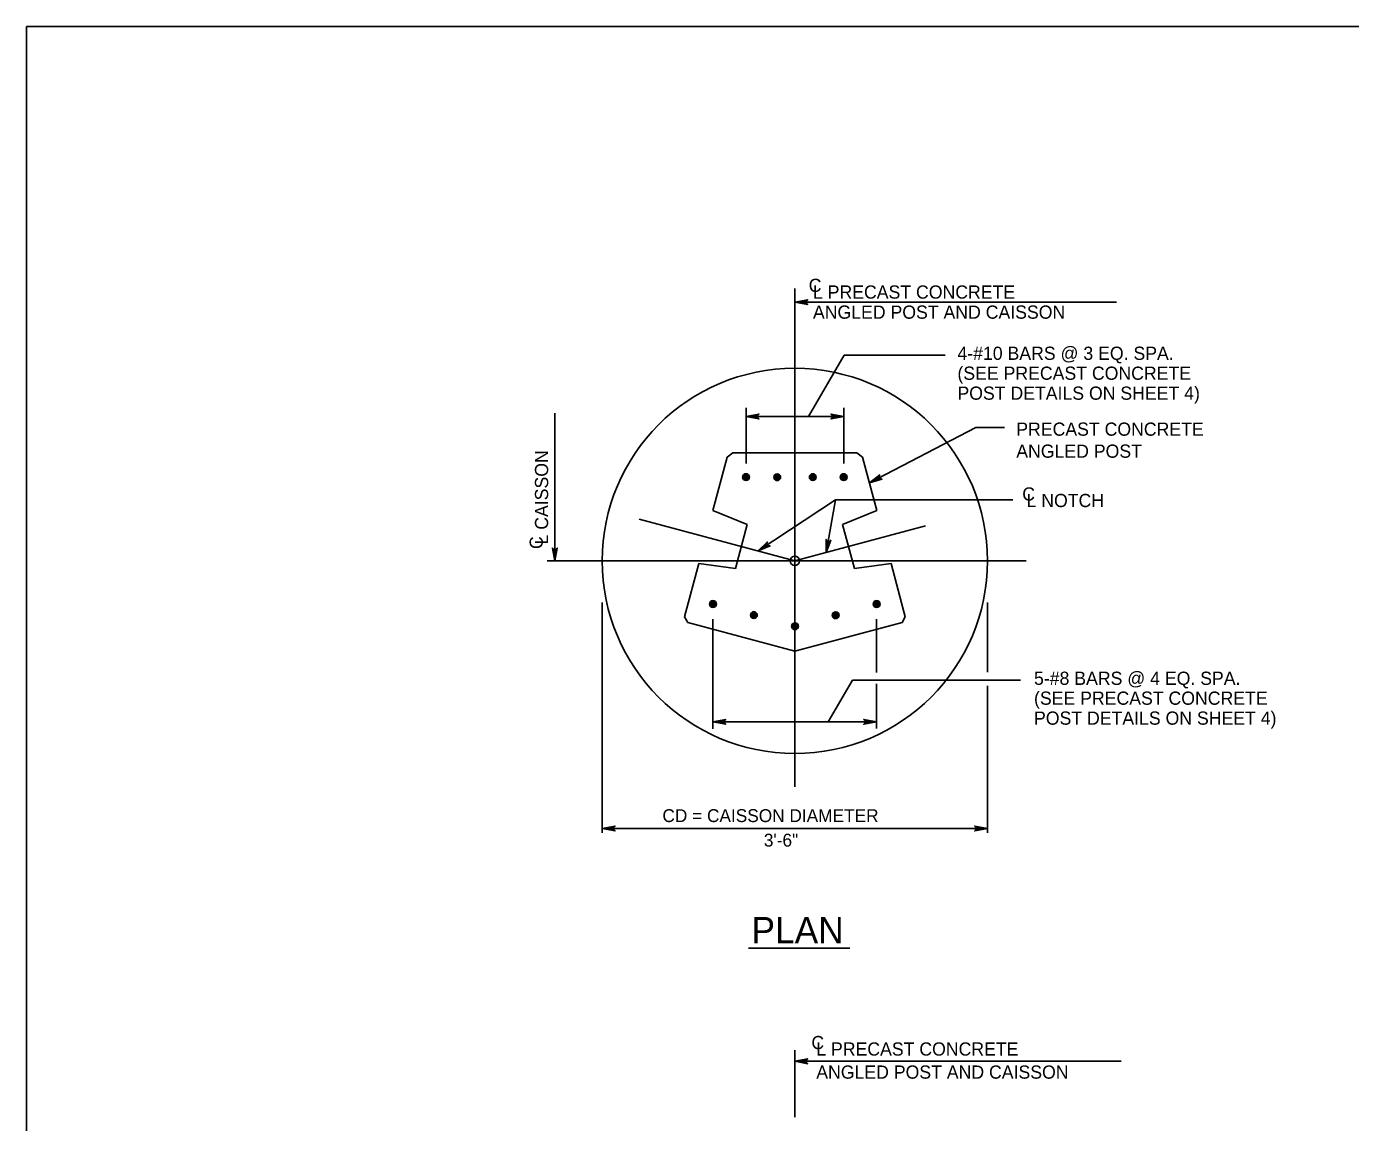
# Model space of a CAD drawing. Extents: x 3351 to 8430, y -3586 to 1457.
# Drawn here: x 3801.3 to 4109.3, y -2668.3 to -2413.3 of the extents above; entities that cross this region are included whole.
import ezdxf

# ---------------------------------------------------------------- set-up
doc = ezdxf.new("R2010")
doc.units = 0
doc.layers.add('1', color=7, linetype='Continuous')
doc.layers.add('2', color=7, linetype='Continuous')

msp = doc.modelspace()

# ---------------------------------------------------------------- linework, layer by layer
at = {"layer": '1'}
for p, q in [((3980.03, -2590.15), (3980.03, -2474.23)), ((3980.03, -2477.43), (4054.86, -2477.43)), ((3983.23, -2504.02), (3991.47, -2489.75)), ((3991.47, -2489.75), (4015, -2489.75)), ((3924.21, -2503.29), (3924.21, -2537.62)), ((3968.67, -2514.98), (3968.67, -2502.03)), ((3991.4, -2514.98), (3991.4, -2502.03)), ((3968.67, -2504.02), (3991.4, -2504.02)), ((3997.37, -2519.48), (4022.14, -2506.61)), ((4022.14, -2506.61), (4028.79, -2506.61)), ((3964.29, -2513.53), (3965.64, -2512.5)), ((3965.64, -2512.5), (3994.43, -2512.5)), ((3994.43, -2512.5), (3995.78, -2513.53)), ((3960.98, -2525.89), (3964.29, -2513.53)), ((3995.78, -2513.53), (3999.09, -2525.89)), ((3989.49, -2523.43), (3971.46, -2535.32)), ((3989.49, -2523.43), (3987.32, -2535.67)), ((3989.49, -2523.43), (4030.76, -2523.43)), ((3943.82, -2527.92), (3980.03, -2537.62)), ((3968.95, -2529.13), (3960.98, -2525.89)), ((3999.09, -2525.89), (3991.12, -2529.13)), ((3966.19, -2539.43), (3968.95, -2529.13)), ((4010.39, -2529.49), (3980.03, -2537.62)), ((3991.12, -2529.13), (3993.88, -2539.43)), ((3922.43, -2537.62), (4033.86, -2537.62)), ((3954.35, -2550.61), (3957.67, -2538.25)), ((3957.67, -2538.25), (3966.19, -2539.43)), ((3980.03, -2537.62), (3980.03, -2537.62)), ((3993.88, -2539.43), (4002.4, -2538.25)), ((4002.4, -2538.25), (4005.71, -2550.61)), ((3935.23, -2547.32), (3935.23, -2600.91)), ((4024.83, -2547.32), (4024.83, -2563.49)), ((3955.11, -2551.92), (3954.35, -2550.61)), ((3980.03, -2558.6), (3955.11, -2551.92)), ((3960.99, -2576.65), (3960.99, -2551.15)), ((4004.96, -2551.92), (3980.03, -2558.6)), ((3999.05, -2563.58), (3999.05, -2551.15)), ((4005.71, -2550.61), (4004.96, -2551.92)), ((3987.81, -2575.05), (3993.41, -2565.36)), ((3993.41, -2565.36), (4032.5, -2565.36)), ((3999.05, -2576.6), (3999.05, -2566.24)), ((4024.83, -2566.65), (4024.83, -2600.91)), ((3960.99, -2575.05), (3999.05, -2575.05)), ((3935.23, -2599.86), (4024.83, -2599.86)), ((3969.28, -2627.74), (3992.81, -2627.74)), ((3980.03, -2651.46), (3980.03, -2667.02)), ((3980.03, -2654.02), (4055.92, -2654.02))]:
    msp.add_line(p, q, dxfattribs=at)
for points in [[(3980.03, -2477.43), (3983.02, -2476.87), (3982.79, -2477.03), (3982.67, -2477.23), (3982.63, -2477.43), (3982.67, -2477.63), (3982.79, -2477.83), (3983.02, -2477.99), (3980.03, -2477.43), (3982.79, -2477.83), (3982.67, -2477.63), (3980.03, -2477.43), (3982.63, -2477.43), (3982.67, -2477.23), (3980.03, -2477.43), (3982.79, -2477.03)], [(3968.67, -2504.02), (3971.66, -2503.46), (3971.43, -2503.62), (3971.31, -2503.82), (3971.27, -2504.02), (3971.31, -2504.22), (3971.43, -2504.42), (3971.66, -2504.58), (3968.67, -2504.02), (3971.43, -2504.42), (3971.31, -2504.22), (3968.67, -2504.02), (3971.27, -2504.02), (3971.31, -2503.82), (3968.67, -2504.02), (3971.43, -2503.62)], [(3991.4, -2504.02), (3988.41, -2504.58), (3988.64, -2504.42), (3988.76, -2504.22), (3988.8, -2504.02), (3988.76, -2503.82), (3988.64, -2503.62), (3988.41, -2503.46), (3991.4, -2504.02), (3988.64, -2503.62), (3988.76, -2503.82), (3991.4, -2504.02), (3988.8, -2504.02), (3988.76, -2504.22), (3991.4, -2504.02), (3988.64, -2504.42)], [(3997.37, -2519.48), (3999.76, -2517.61), (3999.63, -2517.86), (3999.62, -2518.09), (3999.68, -2518.28), (3999.8, -2518.45), (4000, -2518.57), (4000.28, -2518.6), (3997.37, -2519.48), (4000, -2518.57), (3999.8, -2518.45), (3997.37, -2519.48), (3999.68, -2518.28), (3999.62, -2518.09), (3997.37, -2519.48), (3999.63, -2517.86)], [(3971.46, -2535.32), (3973.64, -2533.21), (3973.54, -2533.47), (3973.55, -2533.71), (3973.63, -2533.89), (3973.77, -2534.04), (3973.98, -2534.14), (3974.26, -2534.15), (3971.46, -2535.32), (3973.98, -2534.14), (3973.77, -2534.04), (3971.46, -2535.32), (3973.63, -2533.89), (3973.55, -2533.71), (3971.46, -2535.32), (3973.54, -2533.47)], [(3987.32, -2535.67), (3987.29, -2532.63), (3987.41, -2532.89), (3987.58, -2533.04), (3987.77, -2533.11), (3987.98, -2533.11), (3988.19, -2533.03), (3988.39, -2532.83), (3987.32, -2535.67), (3988.19, -2533.03), (3987.98, -2533.11), (3987.32, -2535.67), (3987.77, -2533.11), (3987.58, -2533.04), (3987.32, -2535.67), (3987.41, -2532.89)], [(3924.21, -2537.62), (3923.65, -2534.64), (3923.81, -2534.87), (3924.01, -2534.99), (3924.21, -2535.02), (3924.41, -2534.99), (3924.61, -2534.87), (3924.77, -2534.64), (3924.21, -2537.62), (3924.61, -2534.87), (3924.41, -2534.99), (3924.21, -2537.62), (3924.21, -2535.02), (3924.01, -2534.99), (3924.21, -2537.62), (3923.81, -2534.87)], [(3960.99, -2575.05), (3963.97, -2574.49), (3963.74, -2574.65), (3963.62, -2574.85), (3963.59, -2575.05), (3963.62, -2575.25), (3963.74, -2575.45), (3963.97, -2575.61), (3960.99, -2575.05), (3963.74, -2575.45), (3963.62, -2575.25), (3960.99, -2575.05), (3963.59, -2575.05), (3963.62, -2574.85), (3960.99, -2575.05), (3963.74, -2574.65)], [(3999.05, -2575.05), (3996.06, -2575.61), (3996.29, -2575.45), (3996.41, -2575.25), (3996.45, -2575.05), (3996.41, -2574.85), (3996.29, -2574.65), (3996.06, -2574.49), (3999.05, -2575.05), (3996.29, -2574.65), (3996.41, -2574.85), (3999.05, -2575.05), (3996.45, -2575.05), (3996.41, -2575.25), (3999.05, -2575.05), (3996.29, -2575.45)], [(3935.23, -2599.86), (3938.22, -2600.42), (3938.1, -2600.34), (3937.99, -2600.26), (3937.93, -2600.16), (3937.87, -2600.06), (3937.85, -2599.96), (3937.83, -2599.86), (3937.85, -2599.76), (3937.87, -2599.66), (3937.93, -2599.56), (3937.99, -2599.46), (3938.1, -2599.38), (3938.22, -2599.3), (3935.23, -2599.86), (3938.1, -2599.38), (3937.99, -2599.46), (3935.23, -2599.86), (3937.93, -2599.56), (3937.87, -2599.66), (3935.23, -2599.86), (3937.85, -2599.76), (3937.83, -2599.86), (3935.23, -2599.86), (3937.85, -2599.96), (3937.87, -2600.06), (3935.23, -2599.86), (3937.93, -2600.16), (3937.99, -2600.26), (3935.23, -2599.86), (3938.1, -2600.34)], [(4024.83, -2599.86), (4021.85, -2599.3), (4021.97, -2599.38), (4022.08, -2599.46), (4022.14, -2599.56), (4022.2, -2599.66), (4022.22, -2599.76), (4022.23, -2599.86), (4022.22, -2599.96), (4022.2, -2600.06), (4022.14, -2600.16), (4022.08, -2600.26), (4021.97, -2600.34), (4021.85, -2600.42), (4024.83, -2599.86), (4021.97, -2600.34), (4022.08, -2600.26), (4024.83, -2599.86), (4022.14, -2600.16), (4022.2, -2600.06), (4024.83, -2599.86), (4022.22, -2599.96), (4022.23, -2599.86), (4024.83, -2599.86), (4022.22, -2599.76), (4022.2, -2599.66), (4024.83, -2599.86), (4022.14, -2599.56), (4022.08, -2599.46), (4024.83, -2599.86), (4021.97, -2599.38)], [(3980.03, -2654.02), (3983.02, -2653.46), (3982.79, -2653.62), (3982.67, -2653.82), (3982.63, -2654.02), (3982.67, -2654.22), (3982.79, -2654.42), (3983.02, -2654.58), (3980.03, -2654.02), (3982.79, -2654.42), (3982.67, -2654.22), (3980.03, -2654.02), (3982.63, -2654.02), (3982.67, -2653.82), (3980.03, -2654.02), (3982.79, -2653.62)]]:
    msp.add_lwpolyline(points, dxfattribs=at)
for centre, radius in [((3980.03, -2537.62), 44.8), ((3968.67, -2518.14), 0.798), ((3968.67, -2518.14), 0.604), ((3968.67, -2518.14), 0.432), ((3968.67, -2518.14), 0.245), ((3968.67, -2518.14), 0.0575), ((3975.92, -2518.15), 0.798), ((3975.92, -2518.15), 0.604), ((3975.92, -2518.15), 0.432), ((3975.92, -2518.15), 0.245), ((3975.92, -2518.15), 0.0575), ((3984.2, -2518.14), 0.798), ((3984.2, -2518.14), 0.604), ((3984.2, -2518.14), 0.432), ((3984.2, -2518.14), 0.245), ((3984.2, -2518.14), 0.0575), ((3991.4, -2518.14), 0.798), ((3991.4, -2518.14), 0.604), ((3991.4, -2518.14), 0.432), ((3991.4, -2518.14), 0.245), ((3991.4, -2518.14), 0.0575), ((3980.03, -2537.62), 1.07), ((3960.99, -2547.66), 0.798), ((3960.99, -2547.66), 0.604), ((3960.99, -2547.66), 0.432), ((3960.99, -2547.66), 0.245), ((3960.99, -2547.66), 0.0575), ((3970.5, -2550.23), 0.798), ((3989.53, -2550.25), 0.798), ((3999.05, -2547.67), 0.798), ((3999.05, -2547.67), 0.604), ((3999.05, -2547.67), 0.432), ((3999.05, -2547.67), 0.245), ((3999.05, -2547.67), 0.0575), ((3970.5, -2550.23), 0.604), ((3970.5, -2550.23), 0.432), ((3970.5, -2550.23), 0.245), ((3970.5, -2550.23), 0.0575), ((3980.07, -2552.81), 0.798), ((3980.07, -2552.81), 0.604), ((3980.07, -2552.81), 0.432), ((3980.07, -2552.81), 0.245), ((3989.53, -2550.25), 0.604), ((3989.53, -2550.25), 0.432), ((3989.53, -2550.25), 0.245), ((3989.53, -2550.25), 0.0575), ((3980.07, -2552.81), 0.0575)]:
    msp.add_circle(centre, radius, dxfattribs=at)
at = {"layer": '2'}
for p, q in [((3801.34, -2977.31), (3801.34, -2413.31)), ((3801.34, -2413.31), (4587.34, -2413.31))]:
    msp.add_line(p, q, dxfattribs=at)

# ---------------------------------------------------------------- texts
at = {"layer": '1'}
for s, height, p in [('C', 3.07, (3983.25, -2475.06)), ('L PRECAST CONCRETE', 3.072, (3984.24, -2476.62)), ('ANGLED POST AND CAISSON', 3.072, (3984.24, -2481.29)), ('4-#10 BARS @ 3 EQ. SPA.', 3.072, (4017.84, -2490.86)), ('(SEE PRECAST CONCRETE', 3.072, (4017.84, -2495.5)), ('POST DETAILS ON SHEET 4)', 3.072, (4017.84, -2500.14)), ('PRECAST CONCRETE', 3.072, (4031.52, -2508.51)), ('ANGLED POST', 3.072, (4031.52, -2513.63)), ('C', 3.07, (4032.91, -2523.59)), ('L NOTCH', 3.072, (4033.91, -2525.11)), ('5-#8 BARS @ 4 EQ. SPA.', 3.072, (4035.65, -2566.46)), ('(SEE PRECAST CONCRETE', 3.072, (4035.65, -2571.09)), ('POST DETAILS ON SHEET 4)', 3.072, (4035.65, -2575.73)), ('CD = CAISSON DIAMETER', 3, (3949.23, -2598.38)), ('3\'-6"', 3, (3972.82, -2604.08)), ('PLAN', 6.144, (3969.93, -2626.6)), ('C', 3.07, (3983.88, -2651.2)), ('L PRECAST CONCRETE', 3.072, (3985.01, -2652.7)), ('ANGLED POST AND CAISSON', 3.072, (3985.01, -2658.07))]:
    msp.add_text(s, height=height, dxfattribs=at).set_placement(p)
for s, height, p in [('L CAISSON', 3.072, (3922.66, -2533.8)), ('C', 3.07, (3921.42, -2534.87))]:
    msp.add_text(s, height=height, rotation=90, dxfattribs=at).set_placement(p)

doc.saveas('drawing.dxf')
